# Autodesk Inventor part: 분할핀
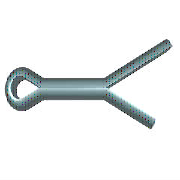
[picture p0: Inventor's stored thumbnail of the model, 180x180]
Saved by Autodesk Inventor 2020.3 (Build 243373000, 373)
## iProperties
IsCustomPart: 1
Created: 2012-02
Part Number: 분할핀
Material: 강철
Description: 분할 핀
Document SubType Name: Modeling
Standard: ISO 1234
Designer: mdu-01
Standard Revision: Second edition 1997-11-01
Standards Organization: ISO
Language: ko-KR
Size Designation: 2 x 14
Categories: <MemberInstance><Categories><Category DisplayName="조임쇠" InternalName="e4da775c-781d-43d5-af7c-5136215cf5a6" Mnemonic="FSTN"><Category DisplayName="핀" InternalNa
Density: 7.85 g/cm^3
Appearance: 파란색 - 벽 페인트 - 광택
Author: mdu-01
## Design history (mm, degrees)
sketch "스케치1"
  geometry: L1 (0, 0.9)-(8, 0.9); L2 (0, -0.9)-(8, -0.9); L3 (8, 0.9)-(14, 3.199); L4 (14, 3.199)-(14.301, 2.414); L5 (14.301, 2.414)-(8, 0); L6 (8, 0)-(16.801, -3.372); L7 (16.801, -3.372)-(16.5, -4.157); L8 (16.5, -4.157)-(8, -0.9); L9 (0, 0)-(-1.832, -0.821); L10 (0, 0)-(-1.832, 0.821); L11 (0, 0.9)-(0, -0.9); L12 (0, 0.9)-(-1.384, 1.604); L13 (0, -0.9)-(-1.384, -1.604); L14 (-4, 0)-(8, 0); L15 (8, 0.9)-(8, -0.9); A1 r 1.8 centre (-2.2, 0) between (-1.384, 1.604) and (-1.384, -1.604); A2 r 0.9 centre (-2.2, 0) between (-1.832, 0.821) and (-1.832, -0.821); 1 further point
  constraints: 30 end point, 5 point on circle, 4 parallel, 4 perpendicular, 4 point on line, 4 tangent, 2 centre point, 2 midpoint, 1 coincident, 1 horizontal
  dimensions: "d0" = 8 distance of L1.start L1.end (= MSIAB); "d1" = 14 horizontal distance of L1.start L3.end (= SNLG); "d2" = 159.037 deg angle of L1 L3; "d3" = 159.037 deg angle of L2 L8; "d4" = 2.5 horizontal distance of L3.end L7.end (= LGDIF); "d5" = 0.9 radius of A2 (= -0.5 x SNND1 + 0.5 x KBR); "d6" = 1.8 radius of A1 (= 0.5 x KBR); "d7" = 0.9 distance from line of L1 L9.start (= 0.5 x SNND1); "d8" = 0.9 distance between parallel lines of L2 L14 (= 0.5 x SNND1); "d9" = 2.2 distance from line of L11 A1.centre (= KOL - 0.5 x KBR)
extrude "본체" new body sketch "스케치1" stored distance "d10" = 1.8 (= SNND1); taper "d11" = 0 deg
workaxis "Work Axis1"
workplane "Work Plane1"
body "Solid1"
fillet "모깎기" dims "d12" = 0.72 (= 0.4 x SNND1)
node "작업 평면2"
other parameters: "SNND" = 2 [user parameter], "SNLG" = 14 [user parameter; used in 1 equation term], "SNND1" = 1.8 [user parameter; used in 5 equation terms], "KBR" = 3.6 [user parameter; used in 3 equation terms], "KOL" = 4 [user parameter; used in 1 equation term], "LGDIF" = 2.5 [user parameter; used in 1 equation term], "MSIAB" = 8 [user parameter; used in 1 equation term], "d15" = 0, "d16" = 0, "d17" = 0, "NNDMAX" = 9 [user parameter], "DSH" = 4 [user parameter], "NNDMIN" = 7 [user parameter]
